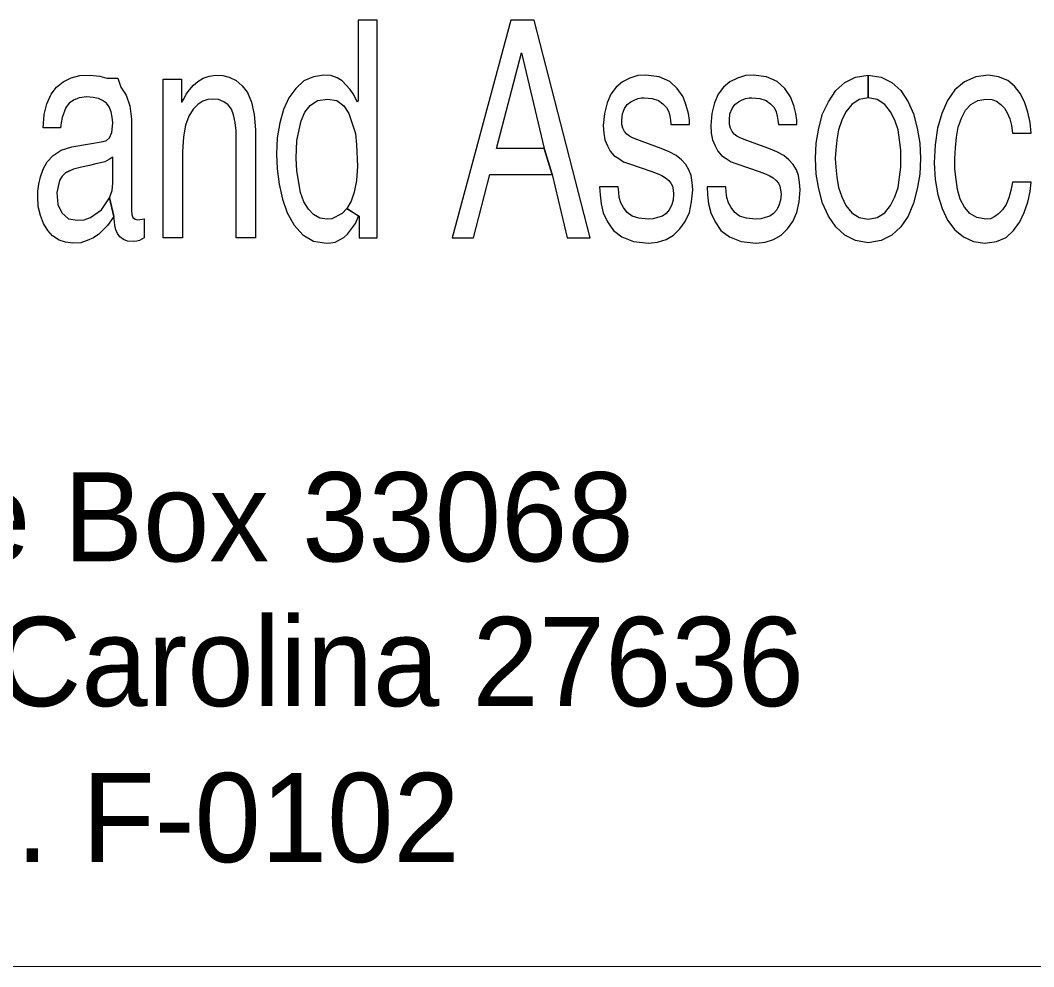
# Model space of a CAD drawing. Extents: x 2431000 to 2534000, y 645879 to 714000.
# Drawn here: x 2465039.21 to 2465074.92, y 679055.24 to 679088.59 of the extents above; entities that cross this region are included whole.
import ezdxf

# ---------------------------------------------------------------- set-up
doc = ezdxf.new("R2010")
doc.units = 0
doc.layers.add('Prop Dimension Text', color=7, linetype='Continuous')

msp = doc.modelspace()

# ---------------------------------------------------------------- linework, layer by layer
at = {"layer": 'Prop Dimension Text'}
for p, q in [((2465044.246, 679080.924), (2465044.246, 679086.512)), ((2465044.246, 679086.512), (2465044.884, 679086.512)), ((2465044.884, 679086.512), (2465044.884, 679085.705)), ((2465045.465, 679086.437), (2465045.653, 679086.549)), ((2465045.653, 679086.549), (2465045.859, 679086.624)), ((2465045.859, 679086.624), (2465046.103, 679086.662)), ((2465046.103, 679086.662), (2465046.346, 679086.643)), ((2465046.346, 679086.643), (2465046.571, 679086.587)), ((2465046.571, 679086.587), (2465046.815, 679086.474)), ((2465060.69, 679086.549), (2465060.428, 679086.418)), ((2465060.971, 679086.643), (2465060.69, 679086.549)), ((2465061.253, 679086.662), (2465060.971, 679086.643)), ((2465061.721, 679086.605), (2465061.253, 679086.662)), ((2465062.096, 679086.437), (2465061.721, 679086.605)), ((2465064.478, 679086.549), (2465064.215, 679086.418)), ((2465064.759, 679086.643), (2465064.478, 679086.549)), ((2465065.04, 679086.662), (2465064.759, 679086.643)), ((2465065.509, 679086.605), (2465065.04, 679086.662)), ((2465065.884, 679086.437), (2465065.509, 679086.605)), ((2465072.878, 679086.605), (2465072.484, 679086.418)), ((2465073.328, 679086.662), (2465072.878, 679086.605)), ((2465073.684, 679086.605), (2465073.328, 679086.662)), ((2465074.003, 679086.474), (2465073.684, 679086.605)), ((2465045.053, 679085.987), (2465045.165, 679086.137)), ((2465045.165, 679086.137), (2465045.315, 679086.305)), ((2465045.315, 679086.305), (2465045.465, 679086.437)), ((2465046.815, 679086.474), (2465047.021, 679086.287)), ((2465047.021, 679086.287), (2465047.209, 679086.043)), ((2465060.203, 679086.23), (2465060.015, 679085.987)), ((2465060.428, 679086.418), (2465060.203, 679086.23)), ((2465062.359, 679086.193), (2465062.096, 679086.437)), ((2465062.565, 679085.893), (2465062.359, 679086.193)), ((2465063.99, 679086.23), (2465063.803, 679085.987)), ((2465064.215, 679086.418), (2465063.99, 679086.23)), ((2465066.146, 679086.193), (2465065.884, 679086.437)), ((2465066.353, 679085.893), (2465066.146, 679086.193)), ((2465072.146, 679086.137), (2465071.884, 679085.762)), ((2465072.484, 679086.418), (2465072.146, 679086.137)), ((2465074.246, 679086.268), (2465074.003, 679086.474)), ((2465074.453, 679086.005), (2465074.246, 679086.268)), ((2465044.903, 679085.705), (2465044.978, 679085.837)), ((2465044.978, 679085.837), (2465045.053, 679085.987)), ((2465045.821, 679085.799), (2465045.634, 679085.743)), ((2465045.971, 679085.818), (2465045.821, 679085.799)), ((2465046.196, 679085.799), (2465045.971, 679085.818)), ((2465046.384, 679085.724), (2465046.196, 679085.799)), ((2465047.209, 679086.043), (2465047.359, 679085.705)), ((2465060.015, 679085.987), (2465059.884, 679085.687)), ((2465060.728, 679085.724), (2465060.84, 679085.78)), ((2465060.84, 679085.78), (2465060.971, 679085.837)), ((2465060.971, 679085.837), (2465061.103, 679085.855)), ((2465061.103, 679085.855), (2465061.196, 679085.855)), ((2465061.196, 679085.855), (2465061.478, 679085.837)), ((2465061.478, 679085.837), (2465061.703, 679085.762)), ((2465062.678, 679085.593), (2465062.565, 679085.893)), ((2465063.803, 679085.987), (2465063.671, 679085.687)), ((2465064.515, 679085.724), (2465064.628, 679085.78)), ((2465064.628, 679085.78), (2465064.759, 679085.837)), ((2465064.759, 679085.837), (2465064.89, 679085.855)), ((2465064.89, 679085.855), (2465064.984, 679085.855)), ((2465064.984, 679085.855), (2465065.265, 679085.837)), ((2465065.265, 679085.837), (2465065.49, 679085.762)), ((2465066.465, 679085.593), (2465066.353, 679085.893)), ((2465072.953, 679085.762), (2465073.234, 679085.818)), ((2465073.234, 679085.818), (2465073.44, 679085.799)), ((2465073.44, 679085.799), (2465073.609, 679085.743)), ((2465074.603, 679085.687), (2465074.453, 679086.005)), ((2465044.903, 679085.705), (2465044.884, 679085.705)), ((2465045.296, 679085.462), (2465045.146, 679085.218)), ((2465045.465, 679085.63), (2465045.296, 679085.462)), ((2465045.634, 679085.743), (2465045.465, 679085.63)), ((2465046.534, 679085.612), (2465046.384, 679085.724)), ((2465046.646, 679085.462), (2465046.534, 679085.612)), ((2465046.721, 679085.255), (2465046.646, 679085.462)), ((2465047.359, 679085.705), (2465047.453, 679085.274)), ((2465059.884, 679085.687), (2465059.79, 679085.312)), ((2465060.428, 679085.293), (2465060.503, 679085.48)), ((2465060.503, 679085.48), (2465060.596, 679085.63)), ((2465060.596, 679085.63), (2465060.728, 679085.724)), ((2465061.703, 679085.762), (2465061.853, 679085.649)), ((2465061.853, 679085.649), (2465061.984, 679085.518)), ((2465061.984, 679085.518), (2465062.059, 679085.368)), ((2465062.753, 679085.312), (2465062.678, 679085.593)), ((2465063.671, 679085.687), (2465063.578, 679085.312)), ((2465064.215, 679085.293), (2465064.29, 679085.48)), ((2465064.29, 679085.48), (2465064.384, 679085.63)), ((2465064.384, 679085.63), (2465064.515, 679085.724)), ((2465065.49, 679085.762), (2465065.64, 679085.649)), ((2465065.64, 679085.649), (2465065.771, 679085.518)), ((2465065.771, 679085.518), (2465065.846, 679085.368)), ((2465066.54, 679085.312), (2465066.465, 679085.593)), ((2465071.884, 679085.762), (2465071.678, 679085.312)), ((2465072.371, 679085.143), (2465072.521, 679085.424)), ((2465072.521, 679085.424), (2465072.709, 679085.63)), ((2465072.709, 679085.63), (2465072.953, 679085.762)), ((2465073.609, 679085.743), (2465073.759, 679085.63)), ((2465073.759, 679085.63), (2465073.89, 679085.499)), ((2465073.89, 679085.499), (2465073.984, 679085.33)), ((2465074.715, 679085.349), (2465074.603, 679085.687)), ((2465045.146, 679085.218), (2465045.034, 679084.899)), ((2465046.778, 679084.993), (2465046.721, 679085.255)), ((2465047.453, 679085.274), (2465047.49, 679084.73)), ((2465059.79, 679085.312), (2465059.753, 679084.88)), ((2465060.409, 679085.068), (2465060.428, 679085.293)), ((2465060.409, 679084.918), (2465060.409, 679085.068)), ((2465062.059, 679085.368), (2465062.096, 679085.218)), ((2465062.096, 679085.218), (2465062.115, 679085.068)), ((2465062.115, 679085.068), (2465062.134, 679084.918)), ((2465062.79, 679085.068), (2465062.753, 679085.312)), ((2465062.79, 679084.918), (2465062.79, 679085.068)), ((2465063.578, 679085.312), (2465063.54, 679084.88)), ((2465064.196, 679085.068), (2465064.215, 679085.293)), ((2465064.196, 679084.918), (2465064.196, 679085.068)), ((2465065.846, 679085.368), (2465065.884, 679085.218)), ((2465065.884, 679085.218), (2465065.903, 679085.068)), ((2465065.903, 679085.068), (2465065.921, 679084.918)), ((2465066.578, 679085.068), (2465066.54, 679085.312)), ((2465066.578, 679084.918), (2465066.578, 679085.068)), ((2465071.678, 679085.312), (2465071.528, 679084.787)), ((2465072.259, 679084.824), (2465072.371, 679085.143)), ((2465073.984, 679085.33), (2465074.078, 679085.124)), ((2465074.078, 679085.124), (2465074.134, 679084.88)), ((2465074.79, 679084.993), (2465074.715, 679085.349)), ((2465045.034, 679084.899), (2465044.959, 679084.487)), ((2465046.815, 679084.693), (2465046.778, 679084.993)), ((2465047.49, 679084.73), (2465047.49, 679080.924)), ((2465059.753, 679084.88), (2465059.771, 679084.618)), ((2465060.446, 679084.787), (2465060.409, 679084.918)), ((2465060.503, 679084.674), (2465060.446, 679084.787)), ((2465062.134, 679084.918), (2465062.79, 679084.918)), ((2465063.54, 679084.88), (2465063.559, 679084.618)), ((2465064.234, 679084.787), (2465064.196, 679084.918)), ((2465064.29, 679084.674), (2465064.234, 679084.787)), ((2465065.921, 679084.918), (2465066.578, 679084.918)), ((2465071.528, 679084.787), (2465071.453, 679084.205)), ((2465072.203, 679084.468), (2465072.259, 679084.824)), ((2465074.134, 679084.88), (2465074.171, 679084.618)), ((2465074.828, 679084.618), (2465074.79, 679084.993)), ((2465044.959, 679084.487), (2465044.921, 679083.962)), ((2465046.815, 679084.355), (2465046.815, 679084.693)), ((2465046.815, 679080.924), (2465046.815, 679084.355)), ((2465059.771, 679084.618), (2465059.809, 679084.374)), ((2465059.809, 679084.374), (2465059.903, 679084.168)), ((2465060.578, 679084.58), (2465060.503, 679084.674)), ((2465060.671, 679084.505), (2465060.578, 679084.58)), ((2465060.784, 679084.449), (2465060.671, 679084.505)), ((2465060.934, 679084.393), (2465060.784, 679084.449)), ((2465061.121, 679084.318), (2465060.934, 679084.393)), ((2465063.559, 679084.618), (2465063.596, 679084.374)), ((2465063.596, 679084.374), (2465063.69, 679084.168)), ((2465064.365, 679084.58), (2465064.29, 679084.674)), ((2465064.459, 679084.505), (2465064.365, 679084.58)), ((2465064.571, 679084.449), (2465064.459, 679084.505)), ((2465064.721, 679084.393), (2465064.571, 679084.449)), ((2465064.909, 679084.318), (2465064.721, 679084.393)), ((2465072.165, 679084.093), (2465072.203, 679084.468)), ((2465074.171, 679084.618), (2465074.828, 679084.618)), ((2465059.903, 679084.168), (2465059.996, 679083.98)), ((2465059.996, 679083.98), (2465060.128, 679083.83)), ((2465061.796, 679084.074), (2465061.121, 679084.318)), ((2465062.078, 679083.962), (2465061.796, 679084.074)), ((2465063.69, 679084.168), (2465063.784, 679083.98)), ((2465063.784, 679083.98), (2465063.915, 679083.83)), ((2465065.584, 679084.074), (2465064.909, 679084.318)), ((2465065.865, 679083.962), (2465065.584, 679084.074)), ((2465071.453, 679084.205), (2465071.415, 679083.568)), ((2465072.146, 679083.718), (2465072.165, 679084.093)), ((2465044.921, 679083.962), (2465044.921, 679080.924)), ((2465060.128, 679083.83), (2465060.296, 679083.718)), ((2465060.296, 679083.718), (2465060.465, 679083.605)), ((2465062.321, 679083.83), (2465062.078, 679083.962)), ((2465062.509, 679083.68), (2465062.321, 679083.83)), ((2465062.659, 679083.512), (2465062.509, 679083.68)), ((2465063.915, 679083.83), (2465064.084, 679083.718)), ((2465064.084, 679083.718), (2465064.253, 679083.605)), ((2465066.109, 679083.83), (2465065.865, 679083.962)), ((2465066.296, 679083.68), (2465066.109, 679083.83)), ((2465066.446, 679083.512), (2465066.296, 679083.68)), ((2465072.146, 679083.343), (2465072.146, 679083.718)), ((2465040.946, 679083.287), (2465040.796, 679083.212)), ((2465040.796, 679083.212), (2465040.946, 679083.287)), ((2465060.465, 679083.605), (2465060.671, 679083.53)), ((2465060.671, 679083.53), (2465061.459, 679083.268)), ((2465061.459, 679083.268), (2465061.646, 679083.193)), ((2465062.771, 679083.324), (2465062.659, 679083.512)), ((2465062.846, 679083.118), (2465062.771, 679083.324)), ((2465064.253, 679083.605), (2465064.459, 679083.53)), ((2465064.459, 679083.53), (2465065.246, 679083.268)), ((2465065.246, 679083.268), (2465065.434, 679083.193)), ((2465066.559, 679083.324), (2465066.446, 679083.512)), ((2465066.634, 679083.118), (2465066.559, 679083.324)), ((2465071.415, 679083.568), (2465071.453, 679082.987)), ((2465072.184, 679082.987), (2465072.146, 679083.343)), ((2465061.646, 679083.193), (2465061.815, 679083.118)), ((2465061.815, 679083.118), (2465061.946, 679083.043)), ((2465061.946, 679083.043), (2465062.059, 679082.949)), ((2465062.059, 679082.949), (2465062.134, 679082.855)), ((2465062.884, 679082.874), (2465062.846, 679083.118)), ((2465065.434, 679083.193), (2465065.603, 679083.118)), ((2465065.603, 679083.118), (2465065.734, 679083.043)), ((2465065.734, 679083.043), (2465065.846, 679082.949)), ((2465065.846, 679082.949), (2465065.921, 679082.855)), ((2465066.671, 679082.874), (2465066.634, 679083.118)), ((2465071.453, 679082.987), (2465071.546, 679082.443)), ((2465072.24, 679082.63), (2465072.184, 679082.987)), ((2465060.278, 679082.724), (2465059.621, 679082.724)), ((2465059.621, 679082.724), (2465059.64, 679082.443)), ((2465060.296, 679082.537), (2465060.278, 679082.724)), ((2465062.134, 679082.855), (2465062.19, 679082.743)), ((2465062.19, 679082.743), (2465062.209, 679082.612)), ((2465062.209, 679082.612), (2465062.228, 679082.462)), ((2465062.865, 679082.199), (2465062.903, 679082.612)), ((2465062.903, 679082.612), (2465062.884, 679082.874)), ((2465064.065, 679082.724), (2465063.409, 679082.724)), ((2465063.409, 679082.724), (2465063.428, 679082.443)), ((2465064.084, 679082.537), (2465064.065, 679082.724)), ((2465065.921, 679082.855), (2465065.978, 679082.743)), ((2465065.978, 679082.743), (2465065.996, 679082.612)), ((2465065.996, 679082.612), (2465066.015, 679082.462)), ((2465066.653, 679082.199), (2465066.69, 679082.612)), ((2465066.69, 679082.612), (2465066.671, 679082.874)), ((2465072.334, 679082.293), (2465072.24, 679082.63)), ((2465074.115, 679082.593), (2465074.04, 679082.33)), ((2465074.171, 679082.893), (2465074.115, 679082.593)), ((2465074.828, 679082.893), (2465074.171, 679082.893)), ((2465074.715, 679082.18), (2465074.79, 679082.555)), ((2465074.79, 679082.555), (2465074.828, 679082.893)), ((2465059.64, 679082.443), (2465059.678, 679082.124)), ((2465060.315, 679082.349), (2465060.296, 679082.537)), ((2465060.371, 679082.162), (2465060.315, 679082.349)), ((2465062.209, 679082.255), (2465062.153, 679082.068)), ((2465062.228, 679082.462), (2465062.209, 679082.255)), ((2465062.79, 679081.824), (2465062.865, 679082.199)), ((2465063.428, 679082.443), (2465063.465, 679082.124)), ((2465064.103, 679082.349), (2465064.084, 679082.537)), ((2465064.159, 679082.162), (2465064.103, 679082.349)), ((2465065.996, 679082.255), (2465065.94, 679082.068)), ((2465066.015, 679082.462), (2465065.996, 679082.255)), ((2465066.578, 679081.824), (2465066.653, 679082.199)), ((2465071.546, 679082.443), (2465071.696, 679081.955)), ((2465072.484, 679082.012), (2465072.334, 679082.293)), ((2465074.04, 679082.33), (2465073.946, 679082.105)), ((2465059.678, 679082.124), (2465059.753, 679081.805)), ((2465060.465, 679081.993), (2465060.371, 679082.162)), ((2465060.596, 679081.824), (2465060.465, 679081.993)), ((2465062.078, 679081.918), (2465061.965, 679081.787)), ((2465062.153, 679082.068), (2465062.078, 679081.918)), ((2465063.465, 679082.124), (2465063.54, 679081.805)), ((2465064.253, 679081.993), (2465064.159, 679082.162)), ((2465064.384, 679081.824), (2465064.253, 679081.993)), ((2465065.865, 679081.918), (2465065.753, 679081.787)), ((2465065.94, 679082.068), (2465065.865, 679081.918)), ((2465071.696, 679081.955), (2465071.884, 679081.543)), ((2465072.671, 679081.787), (2465072.484, 679082.012)), ((2465073.815, 679081.918), (2465073.684, 679081.768)), ((2465073.946, 679082.105), (2465073.815, 679081.918)), ((2465074.584, 679081.824), (2465074.715, 679082.18)), ((2465059.753, 679081.805), (2465059.903, 679081.487)), ((2465059.903, 679081.487), (2465060.109, 679081.187)), ((2465060.765, 679081.693), (2465060.596, 679081.824)), ((2465061.009, 679081.618), (2465060.765, 679081.693)), ((2465061.328, 679081.58), (2465061.009, 679081.618)), ((2465061.515, 679081.599), (2465061.328, 679081.58)), ((2465061.665, 679081.637), (2465061.515, 679081.599)), ((2465061.834, 679081.693), (2465061.665, 679081.637)), ((2465061.965, 679081.787), (2465061.834, 679081.693)), ((2465062.453, 679081.243), (2465062.64, 679081.505)), ((2465062.64, 679081.505), (2465062.79, 679081.824)), ((2465063.54, 679081.805), (2465063.69, 679081.487)), ((2465063.69, 679081.487), (2465063.896, 679081.187)), ((2465064.553, 679081.693), (2465064.384, 679081.824)), ((2465064.796, 679081.618), (2465064.553, 679081.693)), ((2465065.115, 679081.58), (2465064.796, 679081.618)), ((2465065.303, 679081.599), (2465065.115, 679081.58)), ((2465065.453, 679081.637), (2465065.303, 679081.599)), ((2465065.621, 679081.693), (2465065.453, 679081.637)), ((2465065.753, 679081.787), (2465065.621, 679081.693)), ((2465066.24, 679081.243), (2465066.428, 679081.505)), ((2465066.428, 679081.505), (2465066.578, 679081.824)), ((2465071.884, 679081.543), (2465072.146, 679081.205)), ((2465072.915, 679081.637), (2465072.671, 679081.787)), ((2465073.234, 679081.58), (2465072.915, 679081.637)), ((2465073.403, 679081.599), (2465073.234, 679081.58)), ((2465073.553, 679081.674), (2465073.403, 679081.599)), ((2465073.684, 679081.768), (2465073.553, 679081.674)), ((2465074.209, 679081.187), (2465074.434, 679081.487)), ((2465074.434, 679081.487), (2465074.584, 679081.824)), ((2465060.109, 679081.187), (2465060.409, 679080.962)), ((2465062.228, 679081.018), (2465062.453, 679081.243)), ((2465063.896, 679081.187), (2465064.196, 679080.962)), ((2465066.015, 679081.018), (2465066.24, 679081.243)), ((2465072.146, 679081.205), (2465072.446, 679080.962)), ((2465073.946, 679080.943), (2465074.209, 679081.187)), ((2465044.921, 679080.924), (2465044.246, 679080.924)), ((2465047.49, 679080.924), (2465046.815, 679080.924)), ((2465060.409, 679080.962), (2465060.821, 679080.793)), ((2465060.821, 679080.793), (2465061.346, 679080.737)), ((2465061.346, 679080.737), (2465061.665, 679080.774)), ((2465061.665, 679080.774), (2465061.965, 679080.868)), ((2465061.965, 679080.868), (2465062.228, 679081.018)), ((2465064.196, 679080.962), (2465064.609, 679080.793)), ((2465064.609, 679080.793), (2465065.134, 679080.737)), ((2465065.134, 679080.737), (2465065.453, 679080.774)), ((2465065.453, 679080.774), (2465065.753, 679080.868)), ((2465065.753, 679080.868), (2465066.015, 679081.018)), ((2465072.446, 679080.962), (2465072.803, 679080.793)), ((2465072.803, 679080.793), (2465073.196, 679080.737)), ((2465073.196, 679080.737), (2465073.609, 679080.793)), ((2465073.609, 679080.793), (2465073.946, 679080.943)), ((2465119.7, 679055.237), (2464814.7, 679055.25))]:
    msp.add_line(p, q, dxfattribs=at)
for points in [[(2465051.109, 679088.593), (2465051.109, 679085.78), (2465051.09, 679085.705), (2465050.94, 679086.005), (2465050.828, 679086.155), (2465050.696, 679086.305), (2465050.546, 679086.455), (2465050.378, 679086.568), (2465050.153, 679086.643), (2465049.909, 679086.662), (2465049.534, 679086.605), (2465049.196, 679086.455), (2465048.915, 679086.193), (2465048.671, 679085.855), (2465048.484, 679085.443), (2465048.353, 679084.974), (2465048.259, 679084.449), (2465048.24, 679083.887), (2465048.259, 679083.362), (2465048.334, 679082.818), (2465048.446, 679082.293), (2465048.615, 679081.805), (2465048.859, 679081.374), (2465049.159, 679081.037), (2465049.534, 679080.812), (2465050.003, 679080.737), (2465050.153, 679080.755), (2465050.303, 679080.774), (2465050.603, 679080.943), (2465050.734, 679081.055), (2465051.015, 679081.43), (2465051.128, 679081.693), (2465050.715, 679081.955), (2465050.546, 679081.787), (2465050.19, 679081.599), (2465050.021, 679081.58), (2465049.759, 679081.618), (2465049.534, 679081.749), (2465049.365, 679081.937), (2465049.196, 679082.199), (2465049.084, 679082.518), (2465048.953, 679083.287), (2465048.934, 679083.737), (2465048.953, 679084.355), (2465049.103, 679085.049), (2465049.234, 679085.349), (2465049.421, 679085.593), (2465049.684, 679085.762), (2465050.04, 679085.818), (2465050.359, 679085.762), (2465050.603, 679085.574), (2465050.79, 679085.312), (2465051.015, 679084.599), (2465051.053, 679084.205), (2465051.09, 679083.455), (2465051.053, 679082.949), (2465050.978, 679082.537), (2465050.865, 679082.218), (2465050.715, 679081.955), (2465051.146, 679081.693), (2465051.146, 679080.924), (2465051.784, 679080.924), (2465051.784, 679088.593), (2465051.109, 679088.593)], [(2465056.49, 679088.593), (2465054.428, 679080.924), (2465055.178, 679080.924), (2465055.759, 679083.155), (2465057.953, 679083.155), (2465057.671, 679084.074), (2465055.984, 679084.074), (2465056.865, 679087.449), (2465057.671, 679084.074), (2465057.953, 679083.155), (2465058.478, 679080.924), (2465059.284, 679080.924), (2465057.315, 679088.593), (2465056.49, 679088.593)]]:
    msp.add_lwpolyline(points, dxfattribs=at)
for points in [[(2465042.353, 679082.33), (2465042.503, 679081.674), (2465042.278, 679081.355), (2465041.978, 679081.055), (2465041.79, 679080.924), (2465041.565, 679080.83), (2465041.34, 679080.755), (2465041.059, 679080.737), (2465040.796, 679080.774), (2465040.571, 679080.849), (2465040.346, 679080.999), (2465040.178, 679081.187), (2465040.028, 679081.43), (2465039.915, 679081.712), (2465039.84, 679082.03), (2465039.821, 679082.368), (2465039.821, 679082.574), (2465039.859, 679082.818), (2465039.915, 679083.08), (2465040.009, 679083.343), (2465040.159, 679083.605), (2465040.365, 679083.83), (2465040.646, 679084.018), (2465041.021, 679084.13), (2465042.128, 679084.318), (2465042.24, 679084.355), (2465042.353, 679084.449), (2465042.428, 679084.637), (2465042.465, 679084.974), (2465042.446, 679085.18), (2465042.409, 679085.368), (2465042.334, 679085.537), (2465042.24, 679085.668), (2465042.109, 679085.762), (2465041.959, 679085.837), (2465041.771, 679085.874), (2465041.546, 679085.893), (2465041.284, 679085.855), (2465041.078, 679085.78), (2465040.928, 679085.668), (2465040.815, 679085.518), (2465040.684, 679085.162), (2465040.646, 679084.974), (2465040.628, 679084.805), (2465040.009, 679084.805), (2465040.046, 679085.274), (2465040.14, 679085.649), (2465040.29, 679085.987), (2465040.478, 679086.23), (2465040.721, 679086.418), (2465041.003, 679086.568), (2465041.303, 679086.643), (2465041.659, 679086.662), (2465042.015, 679086.624), (2465042.259, 679086.549), (2465042.64, 679086.555), (2465042.746, 679086.23), (2465042.934, 679085.949), (2465043.065, 679085.574), (2465043.121, 679085.105), (2465043.121, 679081.899), (2465043.14, 679081.749), (2465043.178, 679081.637), (2465043.253, 679081.58), (2465043.346, 679081.562), (2465043.571, 679081.599), (2465043.571, 679080.924), (2465043.403, 679080.83), (2465043.309, 679080.812), (2465043.196, 679080.793), (2465042.99, 679080.812), (2465042.84, 679080.868), (2465042.709, 679080.962), (2465042.634, 679081.074), (2465042.578, 679081.205), (2465042.54, 679081.355), (2465042.521, 679081.505), (2465042.503, 679081.674), (2465042.353, 679082.33), (2465042.446, 679082.593), (2465042.465, 679082.855), (2465042.465, 679083.774), (2465042.353, 679083.699), (2465042.184, 679083.605), (2465042.034, 679083.568), (2465041.865, 679083.53), (2465041.64, 679083.474), (2465041.359, 679083.418), (2465041.078, 679083.343), (2465040.796, 679083.212), (2465040.684, 679083.099), (2465040.59, 679082.949), (2465040.496, 679082.518), (2465040.534, 679082.105), (2465040.665, 679081.805), (2465040.909, 679081.599), (2465041.228, 679081.543), (2465041.453, 679081.562), (2465041.678, 679081.637), (2465042.071, 679081.918)], [(2465069.09, 679086.662), (2465069.09, 679085.855), (2465068.771, 679085.799), (2465068.509, 679085.63), (2465068.303, 679085.368), (2465068.153, 679085.068), (2465068.04, 679084.73), (2465067.984, 679084.374), (2465067.946, 679084.018), (2465067.928, 679083.718), (2465067.946, 679083.418), (2465067.984, 679083.062), (2465068.04, 679082.705), (2465068.153, 679082.368), (2465068.303, 679082.068), (2465068.509, 679081.805), (2465068.771, 679081.637), (2465069.09, 679081.58), (2465069.409, 679081.637), (2465069.671, 679081.805), (2465069.878, 679082.068), (2465070.028, 679082.368), (2465070.14, 679082.705), (2465070.196, 679083.062), (2465070.234, 679083.418), (2465070.234, 679084.018), (2465070.196, 679084.374), (2465070.14, 679084.73), (2465070.028, 679085.068), (2465069.878, 679085.368), (2465069.671, 679085.63), (2465069.409, 679085.799), (2465069.09, 679085.855), (2465069.09, 679086.662), (2465069.54, 679086.587), (2465069.915, 679086.399), (2465070.234, 679086.118), (2465070.496, 679085.724), (2465070.684, 679085.293), (2465070.815, 679084.787), (2465070.909, 679084.262), (2465070.928, 679083.718), (2465070.909, 679083.174), (2465070.815, 679082.649), (2465070.684, 679082.143), (2465070.496, 679081.693), (2465070.234, 679081.318), (2465069.915, 679081.018), (2465069.54, 679080.83), (2465069.09, 679080.755), (2465068.64, 679080.83), (2465068.265, 679081.018), (2465067.946, 679081.318), (2465067.684, 679081.693), (2465067.478, 679082.143), (2465067.346, 679082.649), (2465067.253, 679083.174), (2465067.234, 679083.718), (2465067.253, 679084.262), (2465067.346, 679084.787), (2465067.478, 679085.293), (2465067.684, 679085.724), (2465067.946, 679086.118), (2465068.265, 679086.399), (2465068.64, 679086.587)]]:
    msp.add_lwpolyline(points, close=True, dxfattribs=at)

# ---------------------------------------------------------------- texts
for s, p in [('Post Office Box 33068', (2465019.012, 679069.524)), ('Raleigh, North Carolina 27636', (2465010.296, 679064.422))]:
    msp.add_text(s, height=3.14241, rotation=360, dxfattribs=at).set_placement(p)
msp.add_text('PE NO. F-0102', height=3.14249, dxfattribs=at).set_placement((2465025.968, 679058.924))

doc.saveas('drawing.dxf')
